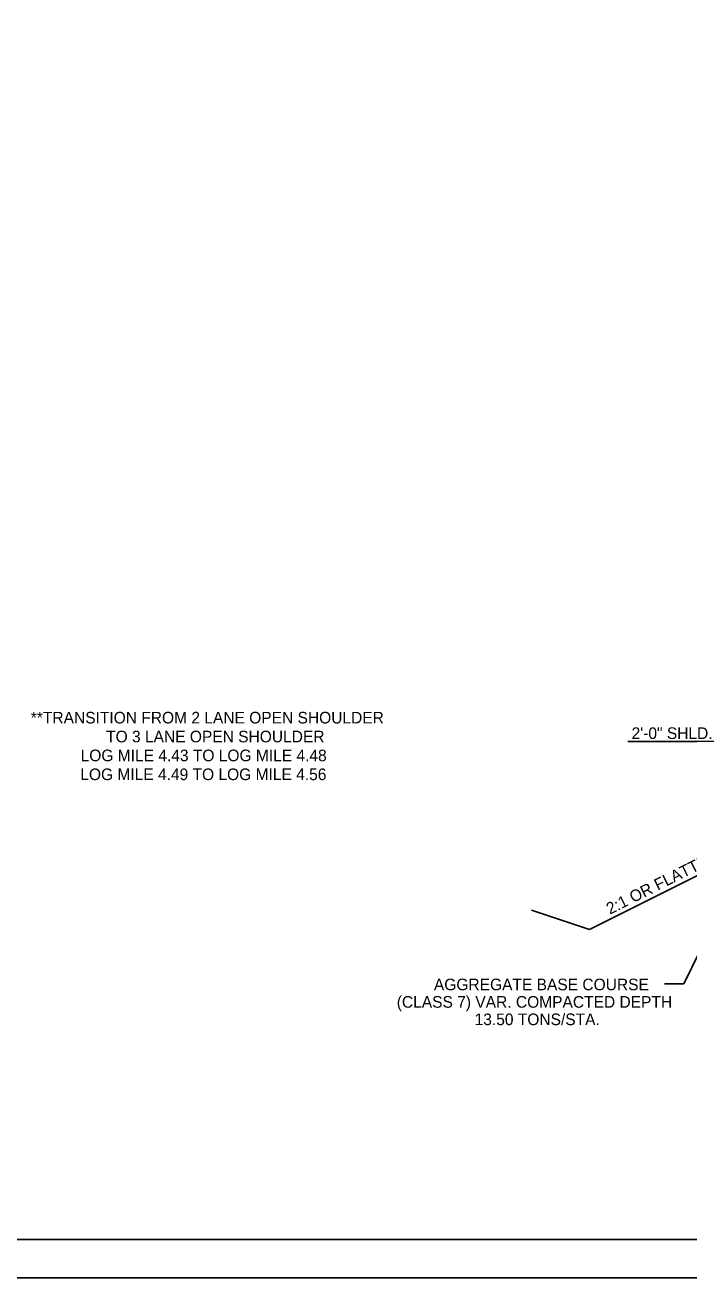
# Model space of a CAD drawing. Extents: x 2263886 to 2266026, y -3122850 to -3121850.
# Drawn here: x 2265264.7 to 2265299, y -3122443.8 to -3122379.1 of the extents above; entities that cross this region are included whole.
import ezdxf

# ---------------------------------------------------------------- set-up
doc = ezdxf.new("R2010")
doc.units = 0
for name, color, linetype in [('_CIVIL_CONSTRUCTION', 7, 'Continuous'), ('R_Border Notes', 7, 'Continuous'), ('R_Border Prem', 7, 'Continuous'), ('R_Draft', 7, 'Continuous')]:
    doc.layers.add(name, color=color, linetype=linetype)

msp = doc.modelspace()

# ---------------------------------------------------------------- linework, layer by layer
at = {"layer": '_CIVIL_CONSTRUCTION'}
msp.add_line((2265192.355, -3122443.817), (2265359.022, -3122443.817), dxfattribs=at)
for points in [[(2265192.352, -3122337.151), (2265359.022, -3122337.151), (2265359.022, -3122443.82), (2265192.352, -3122443.82)], [(2265315.516, -3122339.098), (2265315.516, -3122344.038), (2265333.382, -3122344.038), (2265333.382, -3122345.498), (2265344.981, -3122345.498), (2265344.981, -3122357.664), (2265356.646, -3122357.664), (2265356.646, -3122441.828), (2265198.556, -3122441.828), (2265198.556, -3122339.098)]]:
    msp.add_lwpolyline(points, close=True, dxfattribs=at)
at = {"layer": 'R_Border Notes'}
for p, q in [((2265302.703, -3122421.416), (2265293.86, -3122425.837)), ((2265293.86, -3122425.837), (2265290.86, -3122424.837))]:
    msp.add_line(p, q, dxfattribs=at)
at = {"layer": 'R_Border Prem'}
for p, q in [((2265304.722, -3122416.124), (2265295.838, -3122416.124)), ((2265300.356, -3122425.333), (2265298.735, -3122428.633)), ((2265298.735, -3122428.633), (2265297.735, -3122428.633))]:
    msp.add_line(p, q, dxfattribs=at)
at = {"layer": 'R_Draft'}
msp.add_line((2265356.646, -3122441.828), (2265198.556, -3122441.828), dxfattribs=at)

# ---------------------------------------------------------------- texts
at = {"layer": 'R_Border Prem'}
for s, p in [('**TRANSITION FROM 2 LANE OPEN SHOULDER', (2265265.009, -3122415.194)), ('TO 3 LANE OPEN SHOULDER', (2265268.897, -3122416.169)), ('2\'-0" SHLD.', (2265296.038, -3122415.995)), ('LOG MILE 4.43 TO LOG MILE 4.48', (2265267.581, -3122417.144)), ('LOG MILE 4.49 TO LOG MILE 4.56', (2265267.565, -3122418.119)), ('AGGREGATE BASE COURSE', (2265285.827, -3122428.969)), ('(CLASS 7) VAR. COMPACTED DEPTH', (2265283.909, -3122429.869)), ('13.50 TONS/STA.', (2265287.93, -3122430.769))]:
    msp.add_text(s, height=0.6, dxfattribs=at).set_placement(p)
msp.add_text('2:1 OR FLATTER', height=0.6, rotation=26.565, dxfattribs=at).set_placement((2265294.919, -3122425.067))

doc.saveas('drawing.dxf')
